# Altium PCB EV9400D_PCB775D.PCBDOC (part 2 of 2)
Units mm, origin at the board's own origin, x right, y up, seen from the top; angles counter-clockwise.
Board outline 83 x 87.15 mm, 4 copper layers (Top, L2C, L3C, Bottom), stack 1.546 mm thick; 203 components, 103 nets, 489 pads, 604 vias.
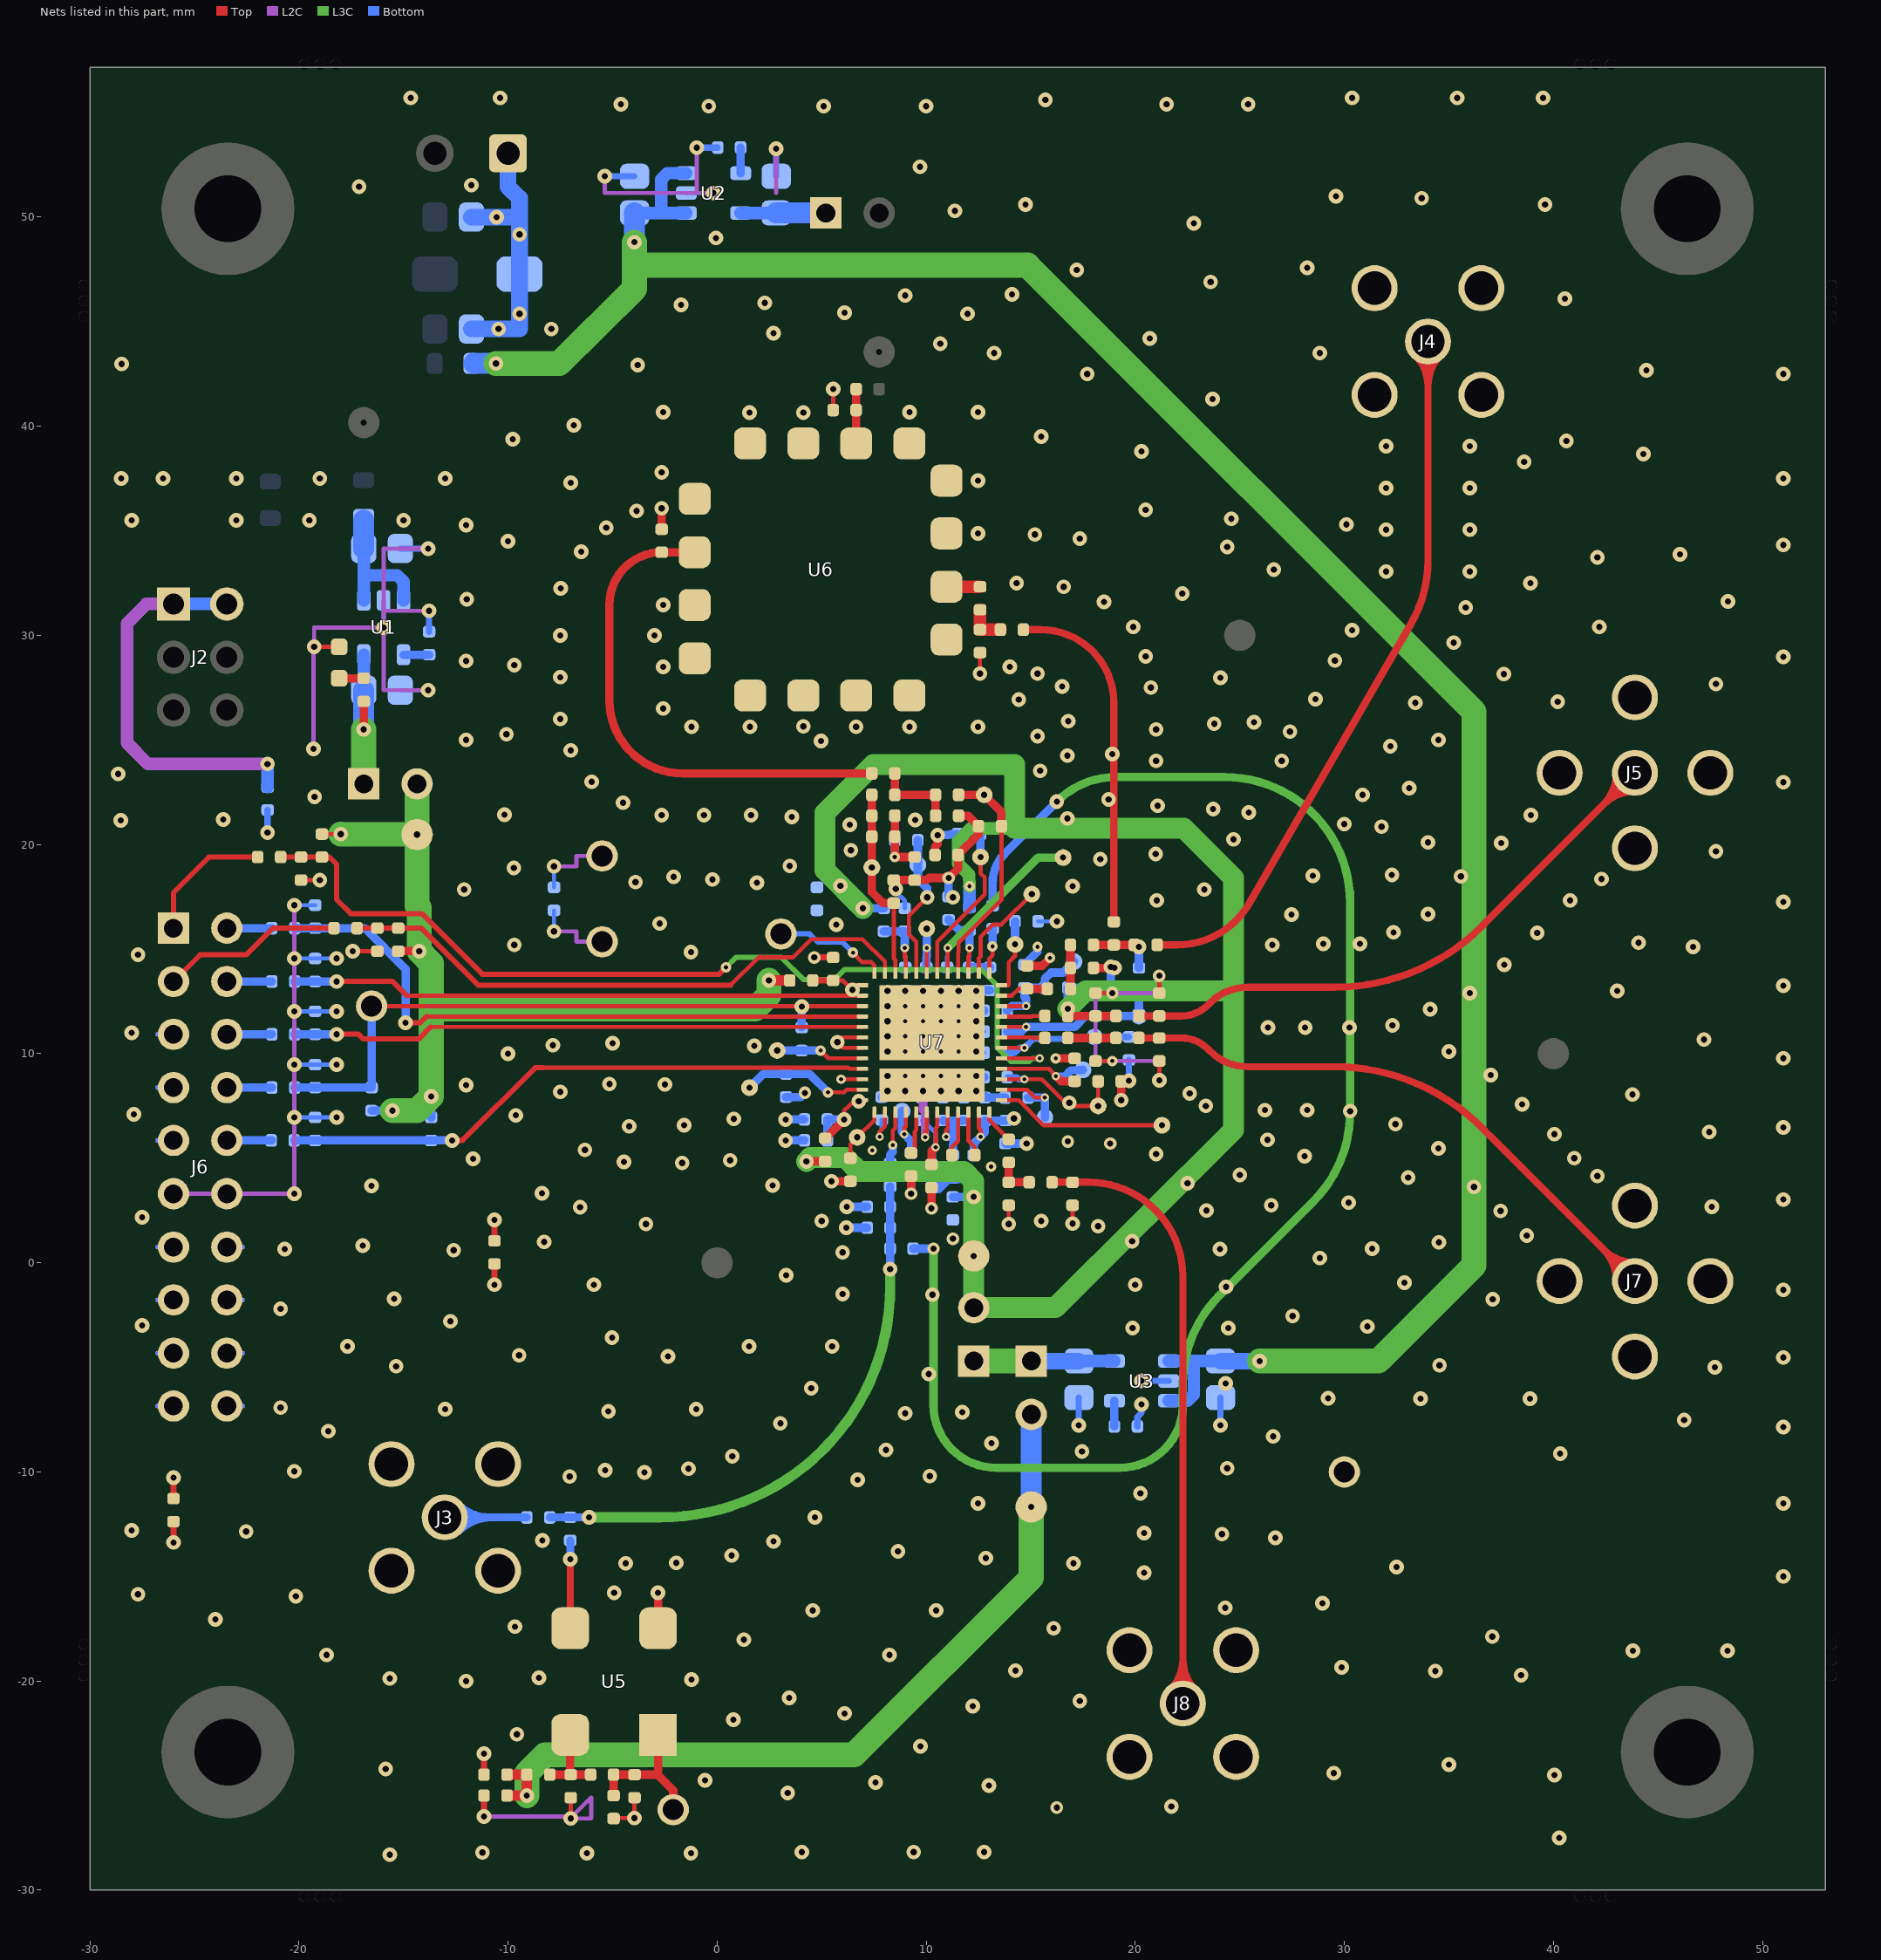
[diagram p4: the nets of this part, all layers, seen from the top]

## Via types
v1: diameter 0.7, hole 0.3, Top to Bottom, tented both sides, 484 vias
v2: diameter 0.6, hole 0.3, Top to L2C, 22 vias
v3: diameter 0.5, hole 0.2, Top to Bottom, tented bottom, 20 vias
v4: diameter 0.7, hole 0.3, Top to L2C, tented both sides, 19 vias
v5: diameter 0.7, hole 0.3, L3C to Bottom, tented both sides, 14 vias
v6: diameter 0.5, hole 0.2, Top to Bottom, tented both sides, 11 vias
v7: diameter 0.4, hole 0.2, Top to Bottom, tented both sides, 10 vias
v8: diameter 0.6, hole 0.3, Top to Bottom, tented both sides, 9 vias
v9: diameter 0.4, hole 0.2, Top to Bottom, tented bottom, 7 vias
v10: diameter 0.45, hole 0.2, Top to Bottom, tented both sides, 3 vias
v11: diameter 0.6, hole 0.3, Top to L2C, tented both sides, 3 vias
v12: diameter 0.7, hole 0.3, Top to Bottom, 1 vias
v13: diameter 0.5, hole 0.2, Top to Bottom, 1 vias

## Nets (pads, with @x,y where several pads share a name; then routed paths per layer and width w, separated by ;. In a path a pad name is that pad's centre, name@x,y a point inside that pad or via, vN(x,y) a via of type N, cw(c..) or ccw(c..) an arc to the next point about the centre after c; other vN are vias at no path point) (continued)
AGND: C4.1 C5.1 C6.1 C7.2 C8.2 C9.1 C10.2 C11.2 C12.2 C15.2 C17.1 C19.2 C21.2 C22.2 C25.2 C28.2 C29.2 C30.2 C31.2 C32.1 C34.2 C35.2 C46.2 C47.2 C48.2 C49.2 C50.2 C51.2 C53.2 C54.2 C56.2 C57.2 C58.2 C59.2 C60.2 C61.2 C62.2 C63.2 C64.2 C70.2 C71.2 C72.2 C73.2 C74.2 C75.2 C77.2 D1.2 J1.1 J3.2 J3.3 J3.4 J3.5 J4.2 J4.3 J4.4 J4.5 J5.2 J5.3 J5.4 J5.5 J7.2 J7.3 J7.4 J7.5 J8.2 J8.3 J8.4 J8.5 R2.1 R6.2 R7.1 R13.2 R18.2 R30.1 R31.1 R36.2 R39.2 R40.1 R41.1 R50.1 R52.1 R54.1 R57.2 R59.1 R60.1 TL2.1 TL3.1 U2.2 U3.2 U5.2 U6.1 U6.3 U6.4 U6.5 U6.6 U6.7 U6.8 U6.9 U6.11 U6.12 U6.13 U6.15 U6.16 U7.18 U7.49 U7.50 | length 116.5
  Top w0.2: v1(-7,-26.575) C15.2@-7,-25.575 ; R6.2@-4.95,-26.55 v1(-3.95,-26.55) C17.1@-3.95,-25.575 ; C21.2@5.55,40.775 v1(5.55,41.775) ; v7(9.95,6) 9.95,6.25 10.025,6.325 U7.18@10.025,7.2 ; v1(12.575,28.175) R13.2@12.575,29.175 ; v1(13.95,1.85) R50.1@13.95,2.75 ; v1(17,1.875) R52.1@17,2.75 ; R40.1@18.1,9.65 v6(18.9,9.65) ; R31.1@18.1,12.9 v11(18.9,12.9) ; v1(21.15,8.725) R41.1@21.15,9.65 ; R30.1@21.15,12.9 v11(21.15,13.725)
  Top w0.3: v1(-26,-13.375) R60.1@-26,-12.375 ; v1(-11.15,-26.475) C71.2@-11.15,-25.475 ; C70.2@-11.15,-24.475 v1(-11.15,-23.475) ; v1(-10.65,-1.05) R59.1@-10.65,-0.05
  Top w0.4: U5.2@-2.825,-17.475 v1(-2.825,-15.775) ; C25.2@-2.65,35.075 v1(-2.65,36.075) ; v1(5.475,3.9) C57.2@6.375,3.9 ; v8(9.275,3.3) C49.2@9.275,4.15 ; v8(10.25,2.6) C59.2@10.25,3.6 ; C77.2@10.425,19.5 10.425,19.9 10.55,20.025 v1(10.55,20.45) ; R57.2@14.825,14.2 15.55,14.2 v6(15.925,14.575) ; v6(16.2,9.775) R39.2@17.1,9.775 ; C34.2@18,14.1 v4(19,14.1) ; v1(19.325,7.775) C75.2@19.325,8.675
  L2C w0.2: v1(-11.15,-26.475) -6.925,-26.475 -6.025,-25.575 -6.025,-26.575 v1(-7,-26.575) ; v1(-7.8,18.95) -6.725,18.95 -6.725,19.45 TL2.1@-5.5,19.45 ; v1(-5.375,51.95) -5.375,51.15 v1(-0.175,51.15) -0.975,51.15 v1(-0.975,53.325) ; 2.825,51.15 v1(2.825,53.275) ; v6(18.9,9.65) 18.1,9.65 ; v11(18.9,12.9) 18.1,12.9 ; v1(21.15,8.725) 21.15,9.65 18.1,9.65 ; v11(21.15,13.725) 21.15,12.9 18.1,12.9 ; 18.1,9.65 18.1,12.9
  L2C w0.4: v2@9.85,8.162 9.85,7.325 9.95,7.225 v7(9.95,6)
  Bottom w0.2: R2.1@-7.8,17.95 v1(-7.8,18.95) ; U2.2@-1.475,51.15 v1(-0.175,51.15) ; v5@8.55,17.75 8.975,17.325 C31.2@8.975,16.95 ; v3@9,12.225 C30.2@9,13.025 ; v3@9.85,12.225 10,12.375 C32.1@10,13.025 ; v3@10.7,12.225 11,12.525 C22.2@11,13.025 ; v3@11.55,10.05 C12.2@12.775,10.05 ; v3@11.55,10.775 11.825,11.05 C58.2@12.775,11.05 ; v3@11.55,11.5 v3@11.7,11.5 ; C29.2@11.95,12.925 C29.2@12.05,13.025 ; C35.2@15.35,16.325 v1(16.25,16.325)
  Bottom w0.3: v1(-5.375,51.95) C6.1@-3.95,51.95 ; v1(-0.975,53.325) C8.2@0.025,53.325 ; C7.2@2.825,51.95 v1(2.825,53.275) ; v1(17.3,-7.775) C10.2@17.3,-6.45 ; v5(19.7,8.7) R36.2@19.7,9.7 ; C11.2@20.1,-7.825 20.1,-7.375 20.3,-7.175 v1(20.3,-6.775) ; v1(20.3,-5.65) U3.2@21.6,-5.65 ; v1(24.075,-7.775) C9.1@24.075,-6.45
  Bottom w0.4: v1(3.275,5.85) C50.2@4.175,5.85 ; v1(3.275,6.85) C51.2@4.175,6.85 ; v1(6.175,1.675) R7.1@7.175,1.675 ; v1(6.2,2.675) C19.2@7.175,2.675 ; C48.2@7.875,7.925 8.875,8.932 v3(9,8.938) v3@8.95,8.9 ; v3@8.925,10.025 v3(9,10.1) ; v8(9.275,3.3) C56.2@9.275,4.15 ; C60.2@9.8,7.9 9.8,8.3 9.85,8.35 v3@9.85,8.888 ; v1(10.55,20.45) 11.1,20.45 11.15,20.5 R18.2@11.5,20.5 ; v3@10.7,8.888 10.7,8.3 10.8,8.2 C64.2@10.8,7.9 ; v3@11.55,12.225 11.95,12.625 C29.2@11.95,12.925 ; v3@11.7,11.5 11.7,12.05 C53.2@12.775,12.05 ; C63.2@11.8,7.9 11.8,8.2 11.55,8.45 11.55,8.888 11.563,8.875 11.825,8.875 ; C29.2@12.05,13.025 C28.2@13.05,13.025 ; C47.2@12.775,8.875 11.825,8.875 ; C61.2@12.8,8 C61.2@12.8,7.9 ; C46.2@13.775,7.9 C61.2@12.8,7.9 ; C62.2@13.8,5.7 v1(14.8,5.7) ; C54.2@14.7,14.25 15.325,14.875 v6(15.325,15.1) ; C72.2@18.825,13.15 v5(18.825,14.15) ; C74.2@20.175,14.1 v5(20.175,15.1) ; 11.825,8.875 C61.2@12.8,7.9
  Bottom w0.8: C5.1@-11.75,44.65 v1(-10.45,44.65) -9.45,44.65 v1(-9.45,45.375) D1.2@-9.45,47.275 v1(-9.45,49.175) -9.45,50 ; C4.1@-11.75,50 v1(-10.55,50) -9.45,50 ; J1.1@-10,53.05 -10,51.45 -9.45,50.9 -9.45,50
  other v1: -15.65,-28.3 -6.225,-28.225 -1.25,-28.225 -11.225,-28.2 4.05,-28.175 9.4,-28.175 12.775,-28.175 40.275,-27.5 21.725,-26 3.375,-25.35 13,-25 7.575,-24.85 -0.575,-24.75 40.05,-24.5 29.5,-24.4 -15.85,-24.2 35,-24 9.725,-23.125 -9.575,-22.55 0.775,-21.85 6.1,-21.55 12.225,-21.2 17.35,-20.95 3.45,-20.8 -12,-20 -1.225,-19.925 -15.65,-19.875 -8.525,-19.85 38.45,-19.725 34.35,-19.525 14.275,-19.5 29.875,-19.35 -18.675,-18.75 8.25,-18.75 43.8,-18.55 48.325,-18.55 1.275,-18.025 37.075,-17.875 16.1,-17.475 -9.675,-17.4 -24,-17.05 4.575,-16.625 10.475,-16.625 24.3,-16.5 28.95,-16.275 -20.15,-15.95 -27.7,-15.85 -4.925,-15.775 51,-15 20.425,-14.825 32.5,-14.55 -4.375,-14.375 17.05,-14.375 -1.95,-14.35 12.85,-14.125 0.7,-14 8.65,-13.8 2.7,-13.325 -8.35,-13.275 26.7,-13.15 24.15,-12.975 20.425,-12.925 -22.525,-12.85 -28,-12.8 4.675,-12.175 12.475,-11.5 51,-11.5 20.25,-11.025 6.725,-10.375 -7.05,-10.225 10.175,-10.2 -3.475,-10.025 -20.225,-9.975 -5.35,-9.925 -1.375,-9.85 24.4,-9.825 0.725,-9.25 40.325,-9.125 17.45,-9.025 8.075,-8.95 13.125,-8.625 26.6,-8.3 -18.6,-8.05 51,-7.85 3.025,-7.675 46.25,-7.525 9,-7.2 11.725,-7.15 -5.2,-7.1 -13,-7 -1,-7 33.65,-6.5 38.875,-6.5 29.225,-6.475 4.5,-6 47.725,-5 -15.35,-4.95 34.55,-4.9 51,-4.525 -2.35,-4.475 -9.475,-4.425 1.525,-4 5.5,-4 -5.025,-3.575 19.875,-3.125 24.45,-3.125 31.1,-3.05 -12.75,-2.8 27.525,-2.55 37.1,-1.75 6,-1.5 51,-1.3 -5.9,-1.05 20,-1.05 32.875,-0.95 3.3,-0.6 6,0.5 24.05,0.65 31.325,0.675 -8.275,1 34.525,0.975 38.725,1.3 18.225,1.75 -3.4,1.85 5,2 15.5,2 37.475,2.475 23.4,2.5 -6.55,2.65 47.575,2.675 26.5,2.75 30.2,2.875 51,3.025 2.65,3.7 33.05,4.075 42.1,4.15 25,4.2 -1.675,4.775 -4.45,4.825 0.625,4.9 41,5 28.1,5.1 21,5.2 34.5,5.475 26.325,5.875 40.05,6.15 47.45,6.25 51,6.475 32.45,6.625 26.2,7.3 28.225,7.3 38.5,7.575 43.775,8.05 22.6,8.1 51,9.775 35,10.1 47.2,10.675 26.35,11.25 28.125,11.25 32.3,11.35 34.1,12.125 43.05,13 51,13.25 37.65,14.25 46.675,15.1 26.55,15.2 29,15.25 44.075,15.3 39.225,15.775 32.35,15.8 27.475,16.65 34,16.675 51,17.25 21.025,17.325 40.8,17.325 23.3,17.85 17,18 1.9,18.175 -3.9,18.2 -0.225,18.325 42.3,18.35 -2.075,18.45 28.5,18.5 32.275,18.55 -9.725,18.875 3.475,18.975 20.975,19.55 47.775,19.675 6.4,19.725 37.5,20.075 34,20.1 24.7,20.25 31.775,20.85 6.35,20.95 30,20.975 9.475,21.175 3.575,21.325 -2.65,21.4 -0.625,21.4 1.625,21.4 38.925,21.4 -10.175,21.425 25.425,21.525 23.725,21.7 21.075,21.85 -4.5,22 30.875,22.375 33.1,22.7 51,22.975 -6,23 15.45,23.525 21,24 27,24 16.75,24.25 -7,24.5 32.2,24.7 4.975,24.95 34.5,25 15.325,25.175 -10.075,25.275 27.4,25.4 21,25.5 -1.225,25.625 1.575,25.625 6.65,25.625 9.2,25.625 12.475,25.625 4.125,25.65 23.775,25.775 25.675,25.85 16.8,25.9 -7.5,26 -2.575,26.5 33.4,26.775 40.2,26.825 14.425,26.925 28.625,26.95 20.75,27.5 16.5,27.55 47.775,27.675 24.075,27.975 -7.5,28 37.625,28.15 15.325,28.175 -2.575,28.5 14,28.5 -9.7,28.575 29.55,28.8 51,28.975 20.5,29 35.225,29.65 -7.5,30 -3,30 30.375,30.25 19.9,30.4 42.2,30.4 35.8,31.325 -2.575,31.45 18.5,31.6 48.35,31.625 22.25,32 -7.475,32.25 16.575,32.325 14.325,32.5 38.9,32.5 32,33.05 36,33.05 26.625,33.15 42.1,33.725 46.05,33.875 -6.5,34 24.4,34.225 51,34.325 -10,34.5 17.35,34.625 15.2,34.825 12.475,34.875 32,35.05 36,35.05 -5.3,35.15 30.1,35.3 24.6,35.575 -3.85,35.95 20.5,36 32,37.05 36,37.05 -7,37.3 12.475,37.4 -28.5,37.5 -26.5,37.5 -23,37.5 -19,37.5 -13,37.5 51,37.5 -2.65,37.8 38.6,38.3 44.3,38.675 20.3,38.8 32,39.05 36,39.05 40.625,39.3 -9.775,39.375 15.5,39.5 -6.85,40.05 -2.575,40.675 1.55,40.65 4.125,40.65 9.2,40.675 12.475,40.675 23.7,41.3 17.7,42.5 51,42.5 44.45,42.675 -3.8,42.925 -28.475,42.975 13.25,43.5 28.825,43.5 10.675,43.95 20.7,44.2 2.7,44.45 -7.925,44.65 11.975,45.375 6.1,45.425 -1.725,45.8 2.275,45.9 40.55,46.1 9,46.25 14.1,46.3 23.6,46.9 17.2,47.475 28.225,47.575 -0.05,49 22.8,49.7 11.375,50.3 14.75,50.6 39.6,50.6 33.7,50.9 29.6,51 -17.125,51.45 -11.75,51.525 9.7,52.4 -0.4,55.3 5.1,55.3 10,55.3 -4.6,55.4 21.5,55.4 25.4,55.4 15.7,55.6 -14.65,55.7 -10.375,55.7 30.375,55.7 35.4,55.7 39.5,55.7
  other v2: 8.15,8.213 9,8.213 9.85,8.213 10.7,8.213 11.55,8.213 12.4,8.213 8.15,8.938 12.4,8.938 8.15,10.1 12.4,10.1 8.15,10.825 12.4,10.825 8.15,11.55 12.4,11.55 8.15,12.275 12.4,12.275 8.15,13 9,13 9.85,13 10.7,13 11.55,13 12.4,13
  other v3: 9.85,8.938 10.7,8.938 11.55,8.938 9.85,10.1 10.7,10.1 11.55,10.1 9,10.825 9.85,10.825 10.7,10.825 11.55,10.825 9,11.55 9.85,11.55 10.7,11.55 11.55,11.55 9,12.275 9.85,12.275 10.7,12.275 11.55,12.275
  other v4: 24.325,-5.775 10.125,-5.325 10.3,-1.525 24.35,-1.15 28.825,0.225 19.85,1.025 36.2,3.625 22.5,3.8 14.2,6.9 30.275,7.25 37,8.975 30.25,11.25 36,12.9 30.75,15.25 11.275,17.475 5.9,18.025 35.575,18.475 16.75,21.25
  other v5: 23.375,7.5 16.85,7.65 6.775,7.725 8.55,17.875 18.325,19.3 18.725,22.15 18.9,24.325
  other v6: 13.1,4.6
  other v8: 16.25,-26.05 18.8,5.7 16.775,5.8
  other v10: 7.425,5.375
  other v11: 11.275,1.15
AVDD: C10.1 JP3.1 JP4.1 U3.5 | length 6.7
  L3C w1.2: JP4.1@12.275,-4.7 JP3.1@15.025,-4.7
  Bottom w0.6: C10.1@17.3,-4.7 U3.5@19,-4.7
  Bottom w0.8: JP3.1@15.025,-4.7 C10.1@17.3,-4.7
AVDD_940: C72.1 C73.1 JP4.2 R16.2 R17.1 R43.1 R44.1 R45.1 R46.2 R47.1 TP5.1 | length 95
  Top w0.4: v1(4.275,4.85) R43.1@5.175,4.85
  L3C w0.6: v6(12.075,18) 12.05,18.55 12.05,18.556 11.525,19.081 11.525,20.175 12.125,20.775 14.225,20.775
  L3C w1: v1(4.275,4.85) 4.45,5.025 6.125,5.025 6.775,4.375 11.8,4.375 12.275,3.9 v1(12.275,3.15) TP5.1@12.275,0.325 JP4.2@12.275,-2.15 16.175,-2.15 24.7,6.35 24.7,13 ; v5(6.975,16.95) 5.15,18.775 5.15,21.5 7.475,23.825 14.225,23.825 14.225,20.775 22.325,20.775 24.7,18.4 24.7,13 ; v5(16.775,12.15) 17.625,13 24.7,13
  Bottom w0.4: v5(6.975,16.95) R17.1@7.975,16.95 ; C73.1@11.275,3.15 v1(12.275,3.15) ; R46.2@12.275,4 R46.2@12.275,4.05 ; v5(16.775,12.15) R44.1@16.775,13.15 C72.1@17.725,13.15
  Bottom w0.5: R45.1@10.275,3.575 10.575,3.575 11.05,4.05 R47.1@11.275,4.05 R46.2@12.275,4.05
  Bottom w0.6: R16.2@12.075,17 v6(12.075,18) ; v1(12.275,3.15) R46.2@12.275,4
CDATA: C42.1 R33.1 U7.2 | length 27.4
  Top w0.2: -14.85,12.775 U7.2@6.95,12.775
  Top w0.25: v1(-18.2,13.45) -15.525,13.45 -14.85,12.775
  Bottom w0.4: R33.1@-20.2,13.45 C42.1@-19.225,13.45 v1(-18.2,13.45)
CPOUT: C23.1 C24.1 C27.1 R9.1 TP6.1 U7.46 | length 9.3
  Top w0.2: C27.1@8.45,17.2 8.45,14.55 8.525,14.475 U7.46@8.525,13.85
  Top w0.4: R9.1@7.4,22.375 C24.1@7.4,21.375 C23.1@7.4,20.375 TP6.1@7.4,18.9 7.4,17.725 7.925,17.2 C27.1@8.45,17.2
CSN: C43.1 R32.1 U7.4 | length 30.7
  Top w0.2: -13.9,11.775 U7.4@6.95,11.775
  Top w0.25: v1(-14.9,11.475) -14.2,11.475 -13.9,11.775
  Bottom w0.4: R32.1@-20.2,16 C43.1@-19.225,16 -16.85,16 -14.9,14.05 v1(-14.9,11.475)
DGND: C1.1 C2.2 C3.2 C36.2 C39.2 C40.2 C41.2 C42.2 C43.2 C45.2 C65.1 C66.2 C67.2 D2.2 J6.11 J6.12 R2.2 R3.1 R54.2 R59.2 R60.2 TL1.1 U1.2 U7.6 U7.7 U7.10 | length 73.4
  Top w0.2: C66.2@-19.9,18.3 v1(-19,18.3) ; v1(-19.275,29.45) D2.2@-18.075,29.45 ; v1(-17.425,14.9) C67.2@-16.25,14.9 ; v10(5.925,8.775) U7.10@6.95,8.775 ; U7.7@6.95,10.275 6.025,10.275 v1(5.75,10.55) 5.975,10.775 U7.6@6.95,10.775
  Top w0.3: R60.2@-26,-11.275 v1(-26,-10.275) ; R59.2@-10.65,1.05 v1(-10.65,2.05) ; v8(4.65,14.6) C36.2@5.55,14.6
  L2C w0.2: J6.11@-26,3.3 J6.12@-23.45,3.3 v1(-20.225,3.3) v1(-20.225,9.475) v1(-20.225,12.025) v1(-20.225,14.55) v1(-20.225,17.1) ; v1(-19.3,24.575) -19.3,29.45 v1(-19.275,29.45) -19.275,30.375 v1(-15.95,30.375) ; v1(-13.825,27.375) -15.95,27.375 v1(-15.95,30.375) ; v1(-13.825,34.15) -15.95,34.15 v1(-15.95,30.375) ; v1(-13.775,31.175) -15.95,31.175 v1(-15.95,30.375) ; v1(-7.8,15.85) -6.725,15.85 -6.725,15.35 TL1.1@-5.5,15.35
  Bottom w0.2: v1(-20.225,6.95) C39.2@-19.225,6.95 v1(-18.2,6.95) ; v1(-20.225,9.475) C40.2@-19.225,9.475 v1(-18.2,9.475) ; v1(-20.225,12.025) C41.2@-19.225,12.025 v1(-18.2,12.025) ; v1(-20.225,14.55) C42.2@-19.225,14.55 v1(-18.2,14.55) ; v1(-20.225,17.1) C43.2@-19.225,17.1 ; v1(-15.95,30.375) U1.2@-15.95,31.675 ; C2.2@-15.15,27.375 v1(-13.825,27.375) ; v1(-7.8,15.85) R2.2@-7.8,16.85
  Bottom w0.3: v1(-21.5,20.575) R3.1@-21.5,21.65 ; C1.1@-15.15,34.15 v1(-13.825,34.15) ; C3.2@-13.775,30.175 v1(-13.775,31.175)
  Bottom w0.4: C45.2@3.3,7.925 4,7.925 v8(4.2,8.125) ; C65.1@4.05,11.25 v5(4.05,12.25)
  other v1: -20.875,-6.925 -17.675,-4 -27.5,-3 -20.875,-2.2 -15.45,-1.725 -12.6,0.6 -20.675,0.65 -16.95,0.825 -27.5,2.175 -8.375,3.325 -16.525,3.675 -11.675,4.975 -6.325,5.4 -4.2,6.525 -1.575,6.575 0.8,6.875 -9.625,7.05 -27.9,7.1 -7.5,8.175 -12,8.5 -2.5,8.525 -5.15,8.55 -10,10 1.775,10.375 -7.85,10.4 -5,10.5 -28,11 -27.7,14.725 -1.25,14.85 -9.7,15.2 5.7,16.175 -2.75,16.225 -12.1,17.85 -28.525,21.15 -23.625,21.2 -19.25,22.275 -12,25 -12,28.775 -11.975,31.725 -12,35.275 -19.5,35.5 -15,35.5
  other v5: 6.475,13.05
DGND_PE0003: J2.1 J2.2 R3.2 | length 19.1
  L2C w0.6: J2.1@-26,31.5 -27.3,31.5 -28.225,30.575 -28.225,24.85 -27.225,23.85 v1(-21.5,23.85)
  Bottom w0.6: J2.1@-26,31.5 J2.2@-23.45,31.5 ; R3.2@-21.5,22.75 v1(-21.5,23.85)
  other v1: -28.65,23.375 -28,35.5 -23,35.5
DVDD3V3: JP1.2 R25.2 R26.2 R28.2 R29.2 R42.2 TP1.1 | length 43.2
  Top w0.2: R42.2@-18.9,20.5 v1(-18,20.5)
  Top w0.4: R26.2@-15.25,14.9 v1(-14.25,14.9)
  Top w0.5: v1(2.475,13.5) R25.2@3.475,13.5
  L3C w1.2: v1(-18,20.5) TP1.1@-14.35,20.475 ; v1(-15.525,7.275) -14.35,7.275 v1(-13.675,7.95) -13.675,12.15 ; JP1.2@-14.35,22.9 TP1.1@-14.35,20.475 ; v1(2.475,13.5) 2.475,12.8 1.825,12.15 -13.675,12.15 ; TP1.1@-14.35,20.475 -14.35,17.075 -14.25,16.975 v1(-14.25,14.9) -13.675,14.325 -13.675,12.15
  Bottom w0.4: R29.2@-16.525,7.275 v1(-15.525,7.275) v1@-15.375,7.275 ; R28.2@-13.675,6.95 v1(-13.675,7.95)
FLCK: R21.1 TP25.1 U7.44 | length 7
  Top w0.2: U7.44@9.525,13.85 9.525,15.35 9.175,15.7 9.175,16.6 v12(10.05,17.475)
  Bottom w0.4: R21.1@9.6,20.2 TP25.1@9.6,19.025 9.6,18.35 10.05,17.9 v12(10.05,17.475)
IRQN: C39.1 R28.1 R37.1 U7.9 | length 29
  Top w0.2: -8.7,9.325 6.275,9.325 6.325,9.275 U7.9@6.95,9.275
  Top w0.25: v1(-12.675,5.85) -12.175,5.85 -8.7,9.325 -8.325,9.325
  Bottom w0.4: R37.1@-20.2,5.85 C39.1@-19.225,5.85 R28.1@-13.675,5.85 v1(-12.675,5.85)
LD: R18.1 TP20.1 U7.42 | length 7.7
  Top w0.2: U7.42@10.525,13.85 10.525,15.35 12.8,17.625 12.8,18.425 12.6,18.625 TP20.1@12.6,19.4
  Bottom w0.4: TP20.1@12.6,19.4 R18.1@12.6,20.5
LOIN: R57.1 R58.1 U7.35 | length 2.3
  Top w0.2: U7.35@13.6,12.775 14.1,12.775 14.425,13.1 R57.1@14.825,13.1
  Top w0.4: R57.1@14.825,13.1 R58.1@15.8,13.1
MCLK: C18.2 U7.15 | length 2.6
  Top w0.2: v10(8.4,5.625) 8.4,6.325 8.525,6.45 U7.15@8.525,7.2
  Bottom w0.4: C18.2@8.275,4.75 8.275,5.175 8.4,5.3 v10(8.4,5.625)
MCLK*: C16.2 C18.1 C19.1 C20.2 C69.1 R7.2 | length 27.4
  L3C w0.492: v1(-6.125,-12.175) -2.725,-12.175 ccw(c-2.725,-1.175) 8.275,-1.175 v1(8.275,-0.3)
  Bottom w0.38: C20.2@-8,-12.175 C16.2@-7.025,-12.175 v1(-6.125,-12.175) ; v1(8.275,-0.3) C69.1@8.275,0.675 R7.2@8.275,1.675 C19.1@8.275,2.675 C18.1@8.275,3.65
NetC1_2: C1.2 L1.2 U1.1 U1.3 | length 6.8
  Bottom w0.6: U1.1@-16.9,31.675 -16.9,32.875 ; C1.2@-16.9,34.15 -16.9,32.875 ; L1.2@-16.9,35.5 L1.2@-16.9,35.55 ; U1.3@-15,31.675 -15,32.575 -15.3,32.875 -16.9,32.875
  Bottom w1: C1.2@-16.9,34.15 L1.2@-16.9,35.5
NetC2_1: C2.1 JP1.1 R1.1 U1.5 | length 7.5
  Top w0.4: v1(-16.9,25.5) R1.1@-16.9,26.85
  L3C w1.2: JP1.1@-16.9,22.9 v1(-16.9,25.5)
  Bottom w0.6: C2.1@-16.9,27.375 U1.5@-16.9,29.075
  Bottom w1: v1(-16.9,25.5) C2.1@-16.9,27.375
NetC3_1: C3.1 U1.4 | length 1.2
  Bottom w0.4: U1.4@-15,29.075 C3.1@-13.775,29.075
NetC6_2: C6.2 C9.2 L3.2 U2.1 U2.3 U3.1 U3.3 | length 113.2
  L3C w1.2: v1(-10.575,43) -7.55,43 -3.95,46.575 -3.95,47.7 ; v1(-3.95,48.8) -3.95,47.7 ; v1(25.95,-4.7) 31.625,-4.7 36.2,-0.125 36.2,26.35 14.85,47.7 -3.95,47.7
  Bottom w0.6: L3.2@-11.75,43 L3.2@-11.625,43 ; C6.2@-3.95,50.2 -2.675,50.2 ; U2.1@-1.475,50.2 -2.675,50.2 ; U2.3@-1.475,52.1 -2.375,52.1 -2.675,51.8 -2.675,50.2 ; U3.3@21.6,-6.6 22.5,-6.6 22.8,-6.3 22.8,-4.7 ; U3.1@21.6,-4.7 22.8,-4.7 ; C9.2@24.075,-4.7 22.8,-4.7
  Bottom w0.8: C9.2@24.075,-4.7 v1(25.95,-4.7)
  Bottom w1: L3.2@-11.625,43 v1(-10.575,43) ; v1(-3.95,48.8) C6.2@-3.95,50.2
NetC7_1: C7.1 JP2.1 U2.5 | length 4.1
  Bottom w0.6: U2.5@1.125,50.2 C7.1@2.825,50.2
  Bottom w1: C7.1@2.825,50.2 JP2.1@5.2,50.2
NetC8_1: C8.1 U2.4 | length 1.2
  Bottom w0.4: U2.4@1.125,52.1 C8.1@1.125,53.325
NetC11_1: C11.1 U3.4 | length 1.2
  Bottom w0.4: C11.1@19,-7.825 U3.4@19,-6.6
NetC12_1: C12.1 R36.1 TP11.1 U7.30 | length 7.2
  Top w0.2: U7.30@13.6,10.275 v9(14.7,10.275)
  Bottom w0.3: C12.1@13.875,10.05 14.25,10.05 14.475,10.275 v9(14.7,10.275) 15.125,10.7 17.425,10.7 17.525,10.8 TP11.1@18.05,10.8 R36.1@19.7,10.8
NetC15_1: C15.1 R4.1 R5.1 U5.4 | length 3.8
  Top w0.4: R4.1@-7.975,-24.475 C15.1@-7.025,-24.475 ; U5.4@-7.025,-22.575 C15.1@-7.025,-24.475 ; R5.1@-6.05,-24.475 C15.1@-7.025,-24.475
NetC16_1: C16.1 U5.3 | length 4.2
  Top w0.345: U5.3@-7.025,-17.475 v1(-7.025,-14.175)
  Bottom w0.38: v1(-7.025,-14.175) C16.1@-7.025,-13.275
NetC17_2: C17.2 R5.2 R6.1 TL4.1 U5.1 | length 7
  Top w0.4: R6.1@-4.95,-25.475 R5.2@-4.95,-24.475 -2.825,-24.475 ; U5.1@-2.825,-22.575 -2.825,-24.475 ; TL4.1@-2.1,-26.15 -2.1,-25.225 -2.805,-24.52 -2.825,-24.5 -2.825,-24.475
NetC20_1: C20.1 J3.1 | length 10.8
  Bottom w0.38: J3.1@-13.025,-12.175 C20.1@-9.1,-12.175 ; J3.1@-12.382,-12.843 cw(c-10.768,-14.457) -10.768,-12.175 ccw(c-10.768,-14.457) J3.1@-12.382,-12.843 ; J3.1@-12.382,-11.557 ccw(c-10.888,-10.063) -10.888,-12.175 cw(c-10.888,-10.063) J3.1@-12.382,-11.557
NetC21_1: C21.1 R8.2 U6.14 | length 2.6
  Top w0.4: U6.14@6.65,39.175 C21.1@6.65,40.775 R8.2@6.65,41.775
NetC23_2: C23.2 C24.2 R15.1 R21.2 | length 3.7
  Top w0.4: C24.2@8.5,21.375 C23.2@8.5,20.375 v6(8.5,19.4) R15.1@9.45,19.4
  Bottom w0.4: v6(8.5,19.4) R21.2@8.5,20.2
NetC25_1: C25.1 R11.1 U6.2 | length 24.6
  Top w0.4: U6.2@-1.075,33.975 C25.1@-2.65,33.975 ccw(c-2.65,31.475) -5.15,31.475 -5.15,26.9 ccw(c-1.65,26.9) -1.65,23.4 R11.1@7.4,23.4
NetC26_2: C26.2 C27.2 C76.1 C77.1 R15.2 R19.1 | length 7.8
  Top w0.4: C27.2@8.45,18.3 R15.2@9.45,18.3 10.025,18.3 10.125,18.4 v8(11.075,18.4) 11.525,18.85 C77.1@11.525,19.5 12.5,20.475 C76.1@12.5,20.875 12,21.375 C26.2@11.55,21.375
  Bottom w0.4: R19.1@11.075,17.5 v8(11.075,18.4)
NetC34_1: C34.1 R23.1 R58.2 | length 2.1
  Top w0.4: R58.2@16.9,13.1 C34.1@16.9,14.1 R23.1@16.9,15.2
NetC35_1: C35.1 TP23.1 U7.36 | length 3.5
  Top w0.2: U7.36@13.6,13.275 13.95,13.275 13.95,14.375 14.25,14.675 TP23.1@14.25,15.225
  Bottom w0.4: TP23.1@14.25,15.225 C35.1@14.25,16.325
NetC36_1: C36.1 R25.1 U7.1 | length 2.5
  Top w0.2: C36.1@5.55,13.5 6,13.5 6.225,13.275 U7.1@6.95,13.275
  Top w0.3: R25.1@4.575,13.5 C36.1@5.55,13.5
NetC37_1: C37.1 U7.33 | length 2.1
  Top w0.2: U7.33@13.6,11.775 15.05,11.775 15.075,11.8 C37.1@15.675,11.8
NetC37_2: C37.2 R27.1 R31.2 | length 2.3
  Top w0.4: C37.2@16.775,11.8 R31.2@18.1,11.8 R27.1@19.075,11.8
NetC38_1: C38.1 U7.31 | length 2.1
  Top w0.2: U7.31@13.6,10.775 15.05,10.775 15.075,10.75 C38.1@15.675,10.75
NetC38_2: C38.2 R38.1 R40.2 | length 2.3
  Top w0.43: C38.2@16.775,10.75 R40.2@18.1,10.75 R38.1@19.075,10.75
NetC45_1: C45.1 TP13.1 U7.11 | length 6.1
  Top w0.2: v6(5.3,8.15) 6.088,8.163 6.2,8.275 U7.11@6.95,8.275
  Bottom w0.4: TP13.1@1.55,8.375 2.2,9.025 C45.1@3.3,9.025 4.425,9.025 v6(5.3,8.15)
NetC46_1: C46.1 TP14.1 U7.26 | length 4
  Top w0.2: U7.26@13.6,8.275 14.825,8.275 15.2,7.9 v9(15.675,7.9)
  Bottom w0.4: C46.1@14.875,7.9 v9(15.675,7.9) TP14.1@15.675,6.95
NetC47_1: C47.1 C75.1 TP26.1 U7.27 | length 7.2
  Top w0.2: U7.27@13.6,8.775 v7(14.7,8.775) 15.525,8.775 16.8,7.5 TP26.1@18.225,7.5 C75.1@18.225,8.675
  Bottom w0.3: C47.1@13.9,8.875 14.325,8.875 14.425,8.775 v7(14.7,8.775)
NetC48_1: C48.1 U7.14 | length 2.1
  Top w0.2: v7(7.775,6.025) 7.775,6.275 8.025,6.523 U7.14@8.025,7.2
  Bottom w0.2: v7(7.775,6.025) 7.775,6.276 7.875,6.376 C48.1@7.875,6.825
NetC49_1: C49.1 U7.17 | length 2
  Top w0.2: C49.1@9.45,5.25 9.45,6.25 9.525,6.35 U7.17@9.525,7.2
NetC50_1: C50.1 C51.1 R43.2 U7.12 | length 4.6
  Top w0.2: v1(6.075,6.85) 6.075,7.275 6.6,7.775 U7.12@6.95,7.775
  Top w0.4: R43.2@5.175,5.95 v1(6.075,6.85)
  Bottom w0.4: C50.1@5.275,5.85 C51.1@5.275,6.85 v1(6.075,6.85)
NetC52_1: C52.1 U7.24 | length 1.6
  Top w0.2: U7.24@13.025,7.2 13.025,6.825 C52.1@13.85,6 ; C52.1@13.85,5.9 C52.1@13.95,5.9
NetC52_2: C52.2 R50.2 R51.1 | length 1.9
  Top w0.4: C52.2@13.95,4.8 R50.2@13.95,3.85 R51.1@14.925,3.85
NetC56_1: C56.1 TP22.1 U7.16 | length 3.3
  Top w0.2: v9(8.95,6.15) 8.95,6.448 9.025,6.523 U7.16@9.025,7.2
  Bottom w0.4: TP22.1@8.85,7.25 8.85,6.25 v9(8.95,6.15) 9.275,5.825 C56.1@9.275,5.25
NetC57_1: C57.1 TP21.1 U7.13 | length 2.7
  Top w0.2: C57.1@6.375,5 6.375,5.675 TP21.1@6.7,6 7.525,6.825 U7.13@7.525,7.2
NetC61_1: C61.1 C62.1 R46.1 U7.23 | length 4.1
  Top w0.2: U7.23@12.525,7.2 12.525,6.425 12.6,6.35 v7(12.6,6.025)
  Bottom w0.4: R46.1@12.275,5.15 12.275,5.7 v7(12.6,6.025) 12.8,6.225 C61.1@12.8,6.8 C62.1@13.8,6.8
NetC65_2: C65.2 TP18.1 U7.8 | length 4.2
  Top w0.2: v6(4.95,10.15) 5.325,9.775 U7.8@6.95,9.775
  Bottom w0.4: TP18.1@2.875,10.15 C65.2@4.05,10.15 v6(4.95,10.15)
NetC70_1: C70.1 C71.1 JP3.2 R4.2 TP4.1 | length 39.8
  Top w0.5: C71.1@-10.05,-25.475 v1(-9.1,-25.475) R4.2@-9.1,-24.475 C70.1@-10.05,-24.475
  L3C w1.2: v1(-9.1,-25.475) -9.1,-24.4 -8.225,-23.525 6.55,-23.525 15.025,-15.05 TP4.1@15.025,-11.675
  Bottom w1: TP4.1@15.025,-11.675 JP3.2@15.025,-7.25
NetD2_1: D2.1 R1.2 | length 1.2
  Top w0.4: D2.1@-18.075,27.95 R1.2@-16.9,27.95
NetJ4_1: J4.1 R24.2 | length 37.6
  Top w0.345: R24.2@21.05,15.2 22,15.2 ccw(c22,19.2) 25.464,17.2 33.196,30.575 ccw(c28,33.575) 34,33.575 J4.1@34,44.05 ; J4.1@33.374,43.424 cw(c31.863,41.913) 34,41.913 cw(c36.137,41.913) J4.1@34.626,43.424
NetJ5_1: J5.1 R27.2 R30.2 | length 31.3
  Top w0.345: R27.2@20.175,11.8 R30.2@21.15,11.8 22.2,11.8 ccw(c22.2,13.611) 23.48,12.33 23.581,12.431 cw(c25.377,10.635) 25.377,13.175 ; 25.375,13.175 29.525,13.175 ccw(c29.525,23.175) 36.938,16.463 J5.1@43.9,23.425 ; J5.1@43.015,23.425 cw(c40.878,23.425) 42.389,21.914 cw(c43.9,20.403) J5.1@43.9,22.54
NetJ6_1: J6.1 R48.1 | length 6.4
  Top w0.25: J6.1@-26,16 -26,17.7 -24.3,19.4 R48.1@-21.975,19.4
NetJ6_2: J6.2 R32.2 | length 2.2
  Bottom w0.4: J6.2@-23.45,16 R32.2@-21.3,16
NetJ6_3: J6.3 R49.1 | length 8.7
  Top w0.25: J6.3@-26,13.45 -24.725,14.725 -22.525,14.725 -21.25,16 R49.1@-18.325,16
NetJ6_4: J6.4 R33.2 | length 2.2
  Bottom w0.4: J6.4@-23.45,13.45 R33.2@-21.3,13.45
NetJ6_5: J6.5 P1.1 | length 0.7
  Bottom w0.2: P1.1@-26.75,10.925 J6.5@-26,10.925
NetJ6_6: J6.6 R34.2 | length 2.2
  Bottom w0.4: J6.6@-23.45,10.925 R34.2@-21.3,10.925
NetJ6_7: J6.7 P2.1 | length 0.7
  Bottom w0.2: P2.1@-26.75,8.375 J6.7@-26,8.375
NetJ6_8: J6.8 R35.2 | length 2.2
  Bottom w0.4: J6.8@-23.45,8.375 R35.2@-21.3,8.375
NetJ6_9: J6.9 P3.1 | length 0.7
  Bottom w0.2: P3.1@-26.75,5.85 J6.9@-26,5.85
NetJ6_10: J6.10 R37.2 | length 2.2
  Bottom w0.4: J6.10@-23.45,5.85 R37.2@-21.3,5.85
NetJ6_13: J6.13 P4.1 | length 0.7
  Bottom w0.2: P4.1@-26.75,0.75 J6.13@-26,0.75
NetJ6_14: J6.14 P11.1 | length 0.7
  Bottom w0.2: J6.14@-23.45,0.75 P11.1@-22.7,0.75
NetJ6_15: J6.15 P5.1 | length 0.7
  Bottom w0.2: P5.1@-26.75,-1.775 J6.15@-26,-1.775
NetJ6_16: J6.16 P10.1 | length 0.7
  Bottom w0.2: J6.16@-23.45,-1.775 P10.1@-22.7,-1.775
NetJ6_17: J6.17 P6.1 | length 0.7
  Bottom w0.2: P6.1@-26.75,-4.325 J6.17@-26,-4.325
NetJ6_18: J6.18 P9.1 | length 0.7
  Bottom w0.2: J6.18@-23.45,-4.325 P9.1@-22.7,-4.325
NetJ6_19: J6.19 P7.1 | length 0.7
  Bottom w0.2: P7.1@-26.75,-6.85 J6.19@-26,-6.85
NetJ6_20: J6.20 P8.1 | length 0.7
  Bottom w0.2: J6.20@-23.45,-6.85 P8.1@-22.7,-6.85
NetJ7_1: J7.1 R38.2 R41.2 | length 31.3
  Top w0.345: R38.2@20.175,10.75 R41.2@21.15,10.75 22.2,10.75 cw(c22.2,8.939) 23.48,10.22 23.581,10.119 ccw(c25.377,11.915) 25.377,9.375 ; 25.375,9.375 29.525,9.375 cw(c29.525,-0.625) 36.938,6.087 J7.1@43.9,-0.875 ; J7.1@43.015,-0.875 ccw(c40.878,-0.875) 42.389,0.636 ccw(c43.9,2.147) J7.1@43.9,0.01
NetJ8_1: J8.1 R51.2 R52.2 | length 32.6
  Top w0.345: R51.2@16.025,3.85 R52.2@17,3.85 17.775,3.85 cw(c17.775,-0.65) 22.275,-0.65 ; J8.1@21.649,-20.449 ccw(c20.138,-18.938) 22.275,-18.938 ccw(c24.412,-18.938) J8.1@22.901,-20.449 ; J8.1@22.275,-21.075 22.275,-0.65
NetL6_1: L6.1 U7.22 | length 2.2
  Top w0.2: U7.22@12.025,7.2 12.025,5.825 12.325,5.525 L6.1@12.325,5.15
NetL6_2: L6.2 U7.21 | length 2.2
  Top w0.2: L6.2@11.225,5.15 11.225,5.525 11.525,5.825 U7.21@11.525,7.2
NetR10_2: R10.2 R12.1 R13.1 | length 1.9
  Top w0.6: R12.1@12.575,31.225 R13.1@12.575,30.275 R10.2@13.55,30.275
NetR12_2: R12.2 U6.10 | length 1.6
  Top w0.6: U6.10@10.975,32.325 R12.2@12.575,32.325
NetR22_1: R22.1 R23.2 R24.1 | length 2
  Top w0.4: R23.2@18,15.2 R22.1@18.975,15.2 R24.1@19.95,15.2
NetR39_1: R39.1 TP12.1 U7.28 | length 5.2
  Top w0.2: U7.28@13.6,9.275 15.875,9.275 v9(16.2,8.925)
  Top w0.4: v9(16.2,8.925) 16.45,8.675 R39.1@17.1,8.675
  Bottom w0.4: v9(16.2,8.925) 16.625,8.9 16.925,9.2 TP12.1@17.5,9.225
NetR53_1: R53.1 U7.37 | length 2.2
  Top w0.2: U7.37@13.025,13.85 13.025,14.55 13.175,14.7 v6(13.175,15.125)
  Bottom w0.4: v6(13.175,15.125) R53.1@13.175,15.975
NetTL10_1: TL10.1 U7.48 | length 5.5
  Top w0.2: v6(6.5,14.825) 6.95,14.375 7.375,14.375 7.525,14.225 U7.48@7.525,13.85
  Bottom w0.25: TL10.1@3.05,15.725 4.425,15.725 4.825,15.325 6,15.325 v6(6.5,14.825)
NetTP9_1: TP9.1 U7.38 | length 5.1
  Top w0.2: U7.38@12.525,13.85 12.525,14.575 12.6,14.65 12.6,15.575 13.2,16.175 13.6,16.175 TP9.1@15.05,17.625
NetTP15_1: TP15.1 U7.25 | length 8.2
  Top w0.2: U7.25@13.6,7.775 14.425,7.775 15.625,6.575 TP15.1@21.275,6.575
RDATA: C40.1 R29.1 R35.1 TL6.1 U7.3 | length 31.1
  Top w0.2: TL6.1@-16.525,12.275 U7.3@6.95,12.275
  Bottom w0.4: R35.1@-20.2,8.375 C40.1@-19.225,8.375 R29.1@-16.525,8.375 TL6.1@-16.525,12.275
REF_RESETN: C66.1 R42.1 R48.2 U7.29 | length 46
  Top w0.2: U7.29@13.6,9.775 v9(15.425,9.775)
  Top w0.25: R48.2@-20.875,19.4 C66.1@-19.9,19.4 -18.55,19.4 -18.2,19.05 -18.2,17.375 -17.525,16.7 -14.125,16.7 -11.225,13.8 0.1,13.8 v13(0.425,14.125)
  L3C w0.25: v13(0.425,14.125) 0.9,14.6 3.075,14.6 4.125,13.55 5.625,13.55 6.1,14.025 12.625,14.025 13.4,13.25 13.4,10.275 14.05,9.625 14.925,9.625 15.075,9.775 v9(15.425,9.775)
RESETN: C67.1 R26.1 R49.2 U7.47 | length 28.3
  Top w0.2: 0.65,13.275 1.975,14.6 3.625,14.6 4.5,15.475 6.95,15.475 8.025,14.4 U7.47@8.025,13.85
  Top w0.25: R49.2@-17.225,16 C67.1@-16.25,16 R26.1@-15.25,16 -14.15,16 -11.425,13.275 0.65,13.275
SCLK: C41.1 R34.1 U7.5 | length 27.5
  Top w0.2: -13.7,11.275 U7.5@6.95,11.275
  Top w0.25: v1(-18.2,10.925) -17.15,10.925 -16.925,10.7 -14.275,10.7 -13.7,11.275
  Bottom w0.4: R34.1@-20.2,10.925 C41.1@-19.225,10.925 v1(-18.2,10.925)
SVCO_DEC2: C22.1 TP24.1 U7.41 | length 9.5
  Top w0.2: U7.41@11.025,13.85 v7(11.025,15.05)
  L3C w0.4: v7(11.025,15.05) 15.35,19.375 TP24.1@16.55,19.375
  Bottom w0.2: C22.1@11,14.125 11,14.625 11.025,14.65 v7(11.025,15.05)
SVCO_VTUNE: C76.2 R14.1 TP7.1 U7.40 | length 11
  Top w0.2: U7.40@11.525,13.85 11.525,14.825 11.55,14.85 11.55,15.3 13.6,17.35 C76.2@13.6,20.875
  Top w0.4: R14.1@11.55,22.375 TP7.1@12.775,22.375 13.6,21.55 C76.2@13.6,20.875
TEST2: C69.2 R53.2 | length 75.2
  L3C w0.4: v8(10.35,0.675) 10.35,-6.8 ccw(c13.35,-6.8) 13.35,-9.8 19.275,-9.8 ccw(c19.275,-6.8) 22.275,-6.8 ; v1(16.247,22.053) cw(c19.075,19.225) 19.075,23.225 24.275,23.225 cw(c24.275,17.225) 30.275,17.225 ; 22.275,-6.85 22.275,-5.8 cw(c28.275,-5.8) 24.028,-1.562 ; 23.963,-1.619 28.518,2.935 ; 28.518,2.932 ccw(c24.275,7.175) 30.275,7.175 30.275,17.725
  Bottom w0.4: C69.2@9.375,0.675 v8(10.35,0.675) ; R53.2@13.175,17.075 13.175,18.15 cw(c15.175,18.15) 13.761,19.564 v1(16.247,22.053)
VCO_OUT: R10.1 R22.2 | length 16.8
  Top w0.345: R10.1@14.65,30.275 15.475,30.275 cw(c15.475,26.775) 18.975,26.775 R22.2@18.975,16.3
VCO_TUNE: C26.1 R9.2 R11.2 R14.2 | length 4
  Top w0.4: R11.2@8.5,23.4 R9.2@8.5,22.375 R14.2@10.45,22.375 C26.1@10.45,21.375
VDD_LO: C53.1 C54.1 R44.2 TP16.1 U7.34 | length 6.2
  Top w0.2: U7.34@13.6,12.275 v9(14.775,12.275)
  Bottom w0.4: C53.1@13.875,12.05 14.1,12.275 v9(14.775,12.275) 14.775,12.625 14.7,12.7 C54.1@14.7,13.15 R44.2@15.675,13.15 15.675,13.575 15.975,13.875 16.55,13.875 TP16.1@17.075,14.4
VDD_PDCP: C30.1 C31.1 R17.2 U7.45 | length 4
  Top w0.2: v7(8.975,15.05) 8.975,14.594 9.025,14.544 U7.45@9.025,13.85
  Bottom w0.2: v7(8.975,15.05) 8.975,14.675 9.025,14.625 9.025,14.15 C30.1@9,14.125
  Bottom w0.4: R17.2@7.975,15.85 C31.1@8.975,15.85 v7(8.975,15.05)
VDD_RPLL: C59.1 C60.1 R45.2 U7.19 | length 5.1
  Top w0.2: v7(10.45,5.525) 10.45,6.425 10.525,6.5 U7.19@10.525,7.2
  Top w0.4: C59.1@10.25,4.7 10.25,5.325 v7(10.45,5.525)
  Bottom w0.2: C60.1@9.8,6.8 9.857,6.8 10.45,6.207 v7(10.45,5.525)
  Bottom w0.4: R45.2@10.275,4.675 10.275,5.35 v7(10.45,5.525)
VDD_RVCO: C63.1 C64.1 R47.2 U7.20 | length 4.2
  Top w0.2: v7(10.95,6.025) 10.95,6.35 11.025,6.425 U7.20@11.025,7.2
  Bottom w0.4: C64.1@10.8,6.8 11.3,6.8 ; v7(10.95,6.025) 11.3,6.025 11.3,6.8 ; R47.2@11.275,5.15 11.275,5.675 11.3,5.7 11.3,6.05 ; C63.1@11.8,6.8 11.3,6.8
VDD_SVCO: C28.1 C29.1 R16.1 R19.2 U7.39 | length 5.2
  Top w0.2: U7.39@12.025,13.85 12.025,14.65 12.075,14.7 v7(12.075,15.05)
  Bottom w0.2: C29.1@12.05,14.125 12.05,14.625 12.075,14.65 v7(12.075,15.05)
  Bottom w0.4: R19.2@11.075,16.4 11.575,15.9 R16.1@12.075,15.9 v7(12.075,15.05) ; C29.1@12.05,14.125 C28.1@13.05,14.125
VREG_DIV: C32.2 TP8.1 U7.43 | length 3.1
  Top w0.2: U7.43@10.025,13.85 v7(10.025,15.05)
  Bottom w0.4: C32.2@10,14.125 10,14.6 10.025,14.625 v7(10.025,15.05) TP8.1@10.025,15.975
VREG_LO: C58.1 C74.1 TP17.1 U7.32 | length 9
  Top w0.2: U7.32@13.6,11.275 v9(14.775,11.275)
  Bottom w0.4: C58.1@13.875,11.05 14.55,11.05 v9(14.775,11.275) 17.1,11.275 17.625,11.8 TP17.1@20.175,11.8 C74.1@20.175,13
pads on no net: FID1.1 FID2.1 FID3.1 FOOT1.0 FOOT2.0 FOOT3.0 FOOT4.0
copper on no net:
  other v1: 16.375,0.55

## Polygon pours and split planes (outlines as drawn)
DGND_PE0003 on Top "Top-DGND0003" (solid, pour order 34): -29.2,22.45 -29.2,36.3 -20.7,36.3 -20.7,22.45
DGND on Top "Top-DGND" (solid, pour order 35): -29.2,21.95 -20.2,21.95 -20.2,36.3 -11.375,36.3 -11.375,18.925 -9.6,17.15 5.425,17.15 7.275,15.35 7.275,9.225 5.725,7.7 2.525,7.7 0.75,5.925 -4.925,5.925 -10.1,0.75 -11.6,0.75 -23.75,-11.575 -29.2,-11.575
AGND on Top "Top-GNDA" (solid, pour order 36): 52.2,44.575 40.6,56.2 -17.575,56.2 -29.2,44.6 -29.2,36.8 -10.875,36.8 -10.875,19.125 -9.4,17.65 5.675,17.65 7.775,15.55 7.775,9.075 5.9,7.2 2.725,7.2 0.95,5.425 -4.725,5.425 -9.9,0.25 -11.4,0.25 -23.55,-12.075 -29.2,-12.075 -29.2,-17.6 -17.6,-29.2 40.6,-29.2 52.2,-17.6
DGND on L2C "L2C-DGND" (solid, pour order 32): -29.2,21.95 -20.2,21.95 -20.2,36.3 -11.375,36.3 -11.375,18.925 -9.6,17.15 5.425,17.15 7.275,15.35 7.275,9.225 5.725,7.7 2.525,7.7 0.75,5.925 -4.925,5.925 -10.1,0.75 -11.6,0.75 -23.75,-11.575 -29.2,-11.575
DGND_PE0003 on L2C "L2C-DGND0003" (solid, pour order 31): -29.2,22.45 -29.2,36.3 -20.7,36.3 -20.7,22.45
AGND on L2C "L2C-AGND" (solid, pour order 33): 52.2,44.575 40.6,56.2 -17.575,56.2 -29.2,44.6 -29.2,36.8 -10.875,36.8 -10.875,19.125 -9.4,17.65 5.675,17.65 7.775,15.55 7.775,9.075 5.9,7.2 2.725,7.2 0.95,5.425 -4.725,5.425 -9.9,0.25 -11.4,0.25 -23.55,-12.075 -29.2,-12.075 -29.2,-17.6 -17.6,-29.2 40.6,-29.2 52.2,-17.6
AGND on L3C "L3C-AGND" (solid, remove dead copper, pour order 30): 52.2,44.575 40.6,56.2 -11.775,56.175 -11.775,52.4 -12.375,51.8 -12.375,42.25 -10.875,40.75 -10.875,19.125 -9.4,17.65 5.675,17.65 7.775,15.55 7.775,9.075 5.9,7.2 2.725,7.2 0.95,5.425 -4.725,5.425 -9.9,0.25 -11.4,0.25 -23.55,-12.075 -29.2,-12.075 -29.2,-17.6 -17.6,-29.2 40.6,-29.2 52.2,-17.6
DGND on L3C "L3C-DGND" (solid, pour order 29): -29.2,21.95 -20.2,21.95 -20.2,36.3 -11.375,36.3 -11.375,18.925 -9.6,17.15 5.425,17.15 7.275,15.35 7.275,9.225 5.725,7.7 2.525,7.7 0.75,5.925 -4.925,5.925 -10.1,0.75 -11.6,0.75 -23.75,-11.575 -29.2,-11.575
DGND_PE0003 on L3C "L3C-DGND0003" (solid, pour order 28): -29.2,22.45 -29.2,36.3 -20.7,36.3 -20.7,22.45
+V on L3C "L3C+V" (solid, pour order 19): -11.375,36.8 -29.2,36.8 -29.2,44.6 -17.575,56.2 -12.275,56.2 -12.275,52.6 -12.875,52 -12.875,42.05 -11.375,40.55
+V on Bottom "Bot+V" (solid, pour order 23): -11.375,36.8 -29.2,36.8 -29.2,44.6 -17.575,56.2 -12.275,56.2 -12.275,52.6 -12.875,52 -12.875,42.05 -11.375,40.55
DGND on Bottom "Bottom-DGND" (solid, pour order 27): -29.2,21.95 -20.2,21.95 -20.2,36.3 -11.375,36.3 -11.375,18.925 -9.6,17.15 5.425,17.15 7.275,15.35 7.275,9.225 5.725,7.7 2.525,7.7 0.75,5.925 -4.925,5.925 -10.1,0.75 -11.6,0.75 -23.75,-11.575 -29.2,-11.575
DGND_PE0003 on Bottom "Bottom-DGND0003" (solid, pour order 26): -29.2,22.45 -29.2,36.3 -20.7,36.3 -20.7,22.45
AGND on Bottom "Bottom-GNDA" (solid, remove dead copper, pour order 25): 52.2,44.575 40.6,56.2 -11.775,56.175 -11.775,52.4 -12.375,51.8 -12.375,42.25 -10.875,40.75 -10.875,19.125 -9.4,17.65 5.675,17.65 7.775,15.55 7.775,9.075 5.9,7.2 2.725,7.2 0.95,5.425 -4.725,5.425 -9.9,0.25 -11.4,0.25 -23.55,-12.075 -29.2,-12.075 -29.2,-17.6 -17.6,-29.2 40.6,-29.2 52.2,-17.6

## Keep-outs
Board:
  lines w0.127: -30,-30 -30,57 53,57 53,-30 -30,-30

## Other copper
Top:
  pour cut-out: 6.9,13.9 13.65,13.9 13.65,7.15 6.875,7.15
  text "http://www.cmlmicro.com" at 16.425,-28.7 h2.25
L3C:
  region net +V: -22.1,38.15 -15.9,38.15 -12.875,41.175 -12.875,43.75 -14.675,45.55 -17.475,45.55 -22.1,40.925
Bottom:
  region net AGND: 8.45,9.3 8.225,9.075 8.225,8.6 8.45,8.375 12.094,8.375 12.3,8.625 12.3,9.1 12.1,9.3
  region net AGND: 8.45,12.55 8.225,12.325 8.225,9.9 8.45,9.675 12.1,9.675 12.325,9.9 12.325,12.325 12.1,12.55
  text "PCB775D" at 38.3,-28.7 h3
Multi-Layer:
  pour cut-out: -23.4,-27 cw(c-23.4,-23.4) -27,-23.4 cw(c-23.4,-23.4) -23.4,-19.8 cw(c-23.4,-23.4) -19.8,-23.4 cw(c-23.4,-23.4)
  pour cut-out: 46.4,-27 cw(c46.4,-23.4) 42.8,-23.4 cw(c46.4,-23.4) 46.4,-19.8 cw(c46.4,-23.4) 50,-23.4 cw(c46.4,-23.4)
  pour cut-out: 46.4,46.8 cw(c46.4,50.4) 42.8,50.4 cw(c46.4,50.4) 46.4,54 cw(c46.4,50.4) 50,50.4 cw(c46.4,50.4)
  pour cut-out: -23.4,46.8 cw(c-23.4,50.4) -27,50.4 cw(c-23.4,50.4) -23.4,54 cw(c-23.4,50.4) -19.8,50.4 cw(c-23.4,50.4)

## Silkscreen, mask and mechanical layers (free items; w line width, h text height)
Top Silk:
  lines w0.2: -1.625,-1.625 -0.875,-0.875 ; -1.625,1.625 -0.875,0.875 ; 0.875,-0.875 1.625,-1.625 ; 0.875,0.875 1.625,1.625
  text "0V" at -7.475,54.225 h2
  text "+6V" at -18.9,54.15 h2
  text "EV9400" at 16.4,44.15 h4
  text "2GHz" at 19.2,41.65 h3
  text "LO_IN" at 39.525,41.15 h1.5
  text "Integrated" at 16.25,39.35 h3
  text "Synthesizer" at 15.025,36.55 h3
  text "AGND" at -10.125,20.175 h1.27
  text "LOOUT1" at 44.925,16 h1.5
  text "DGND" at -10.175,13.425 h1.27
  text "RDATA" at -17.675,8.3 h1.27
  text "C-BUS" at -20.55,8 h2 r90
  text "LOOUT2" at 35.85,-5.625 h1.5
  text "AGND2" at 26,-13 h1.5
  text "EXT_CLK" at -16.9,-18.875 h1.5
  text "REF_LOOUT" at 26.7,-22.725 h1.5
Bot Silk:
  lines w0.2: -1.625,-1.625 -0.875,-0.875 ; -1.625,1.625 -0.875,0.875 ; 0.875,-0.875 1.625,-1.625 ; 0.875,0.875 1.625,1.625
  text "0V" at -8.025,54.225 h2
  text "+6V" at -12.2,54.125 h2
Top Mask:
  lines w1.2: -1.15,33.975 -2.725,33.975 ccw(c-2.725,31.475) -5.225,31.475 -5.225,26.9 ccw(c-1.725,26.9) -1.725,23.4 7.325,23.4 ; 14.575,30.275 15.4,30.275 cw(c15.4,26.775) 18.9,26.775 18.9,16.3 ; 15.95,3.85 16.925,3.85 17.7,3.85 cw(c17.7,-0.65) 22.2,-0.65 22.2,-21.075 ; 20.2,11.8 21.075,11.8 22.125,11.8 ccw(c22.125,13.611) 23.405,12.33 23.506,12.431 cw(c25.302,10.635) 25.302,13.175 ; 21.05,15.2 22,15.2 ccw(c22,19.2) 25.464,17.2 33.196,30.575 ccw(c28,33.575) 34,33.575 34,44.05 ; 21.574,-20.449 ccw(c20.063,-18.938) 22.2,-18.938 ccw(c24.337,-18.938) 22.826,-20.449 ; 25.3,13.175 29.45,13.175 ccw(c29.45,23.175) 36.863,16.463 43.825,23.425 ; 33.374,43.424 cw(c31.863,41.913) 34,41.913 cw(c36.137,41.913) 34.626,43.424 ; 42.94,23.425 cw(c40.803,23.425) 42.314,21.914 cw(c43.825,20.403) 43.825,22.54
  lines w1.25: 20.175,10.75 21.15,10.75 22.2,10.75 cw(c22.2,8.939) 23.48,10.22 23.581,10.119 ccw(c25.377,11.915) 25.377,9.375 ; 25.375,9.375 29.525,9.375 cw(c29.525,-0.625) 36.938,6.087 43.9,-0.875 ; 43.015,-0.875 ccw(c40.878,-0.875) 42.389,0.636 ccw(c43.9,2.147) 43.9,0.01
CutOut:
  lines w2: -31,-21 -31,-31 -21,-31 ; -31,-17 -31,44 ; -31,48 -31,58 -21,58 ; -17,-31 40,-31 ; -17,58 40,58 ; 44,-31 54,-31 54,-21 ; 44,58 54,58 54,48 ; 54,-17 54,44
eltiT:
  text "Bottom Side" at 57.725,55.75 h1.59 r90
Title:
  text "Top Side" at 57.6,-30.825 h1.59 r90
BoardLine:
  lines w0.2: -30,-30 53,-30 53,57 -30,57 -30,-30
Split Pours:
  lines w0.5: -32,-11.825 -23.65,-11.825 -11.5,0.5 -10,0.5 -4.825,5.675 0.85,5.675 2.625,7.45 5.8,7.45 7.525,9.175 7.525,15.45 5.525,17.4 -9.5,17.4 -11.125,19.025 -11.125,36.55 ; -32,22.2 -20.45,22.2 -20.45,36.55 ; -32,36.55 -20.45,36.55 ; -12.025,58 -12.025,52.5 -12.625,51.9 -12.625,42.15 -11.125,40.65 -11.125,36.55 ; -20.45,36.55 -11.125,36.55
Bottom Courtyard:
  circle w0.2: c-14.9,11.475 r0.475
Bk-off:
  lines w3.1: -6.2,-12.175 -2.8,-12.175 ; -2.725,-12.15 ccw(c-2.725,-1.15) 8.275,-1.15 ; -1.15,33.975 -2.725,33.975 ccw(c-2.725,31.475) -5.225,31.475 -5.225,26.9 ccw(c-1.725,26.9) -1.725,23.4 7.325,23.4 ; 8.275,-1.175 8.275,-0.3 ; 14.575,30.275 15.4,30.275 cw(c15.4,26.775) 18.9,26.775 18.9,16.3 ; 15.95,3.85 16.925,3.85 17.7,3.85 cw(c17.7,-0.65) 22.2,-0.65 22.2,-21.075 ; 20.1,11.8 21.075,11.8 22.125,11.8 ccw(c22.125,13.611) 23.405,12.33 23.506,12.431 cw(c25.302,10.635) 25.302,13.175 ; 20.175,10.75 22.2,10.75 cw(c22.2,8.939) 23.48,10.22 23.581,10.119 ccw(c25.377,11.915) 25.377,9.375 ; 21.05,15.2 22,15.2 ccw(c22,19.2) 25.464,17.2 33.196,30.575 ccw(c28,33.575) 34,33.575 34,44.05 ; 21.574,-20.449 ccw(c20.063,-18.938) 22.2,-18.938 ccw(c24.337,-18.938) 22.826,-20.449 ; 25.3,13.175 29.45,13.175 ccw(c29.45,23.175) 36.863,16.463 43.825,23.425 ; 25.375,9.375 29.525,9.375 cw(c29.525,-0.625) 36.938,6.087 43.9,-0.875 ; 33.374,43.424 cw(c31.863,41.913) 34,41.913 cw(c36.137,41.913) 34.626,43.424 ; 42.94,23.425 cw(c40.803,23.425) 42.314,21.914 cw(c43.825,20.403) 43.825,22.54 ; 43.015,-0.875 ccw(c40.878,-0.875) 42.389,0.636 ccw(c43.9,2.147) 43.9,0.01

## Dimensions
-30,-30 to 0,0 on Dimensions
-30,-30 to 0,0 on Dimensions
